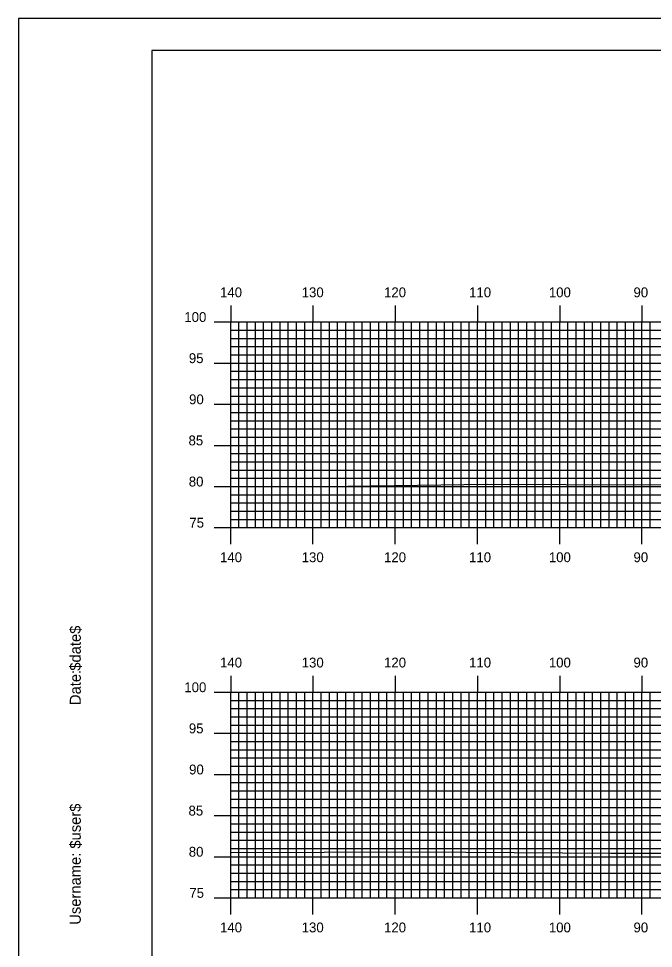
# Model space of a CAD drawing. Extents: x 1757069 to 1757412, y 442591 to 442811.
# Drawn here: x 1757068.8 to 1757146, y 442697.5 to 442810.5 of the extents above; entities that cross this region are included whole.
import ezdxf

# ---------------------------------------------------------------- set-up
doc = ezdxf.new("R2010")
doc.units = 0
for name, color, linetype in [('BORDER', 7, 'Continuous'), ('H_V ANNOTATION', 7, 'Continuous'), ('MAJOR', 7, 'Continuous'), ('MINOR', 7, 'Continuous'), ('PLOT BOUNDARY', 7, 'Continuous'), ('S_Roadway_Centerline', 7, 'Continuous')]:
    doc.layers.add(name, color=color, linetype=linetype)

msp = doc.modelspace()

# ---------------------------------------------------------------- linework, layer by layer
at = {"layer": 'BORDER'}
msp.add_lwpolyline([(1757085, 442596.67), (1757405, 442596.67), (1757405, 442806.67), (1757085, 442806.67)], close=True, dxfattribs=at)
at = {"layer": 'MAJOR'}
for p, q in [((1757094.6, 442775.67), (1757094.6, 442773.67)), ((1757104.6, 442775.67), (1757104.6, 442773.67)), ((1757114.6, 442775.67), (1757114.6, 442773.67)), ((1757124.6, 442775.67), (1757124.6, 442773.67)), ((1757134.6, 442775.67), (1757134.6, 442773.67)), ((1757144.6, 442775.67), (1757144.6, 442773.67)), ((1757092.59, 442773.67), (1757094.6, 442773.67)), ((1757094.6, 442773.67), (1757374.6, 442773.67)), ((1757094.6, 442748.67), (1757094.6, 442773.67)), ((1757094.6, 442748.67), (1757094.6, 442773.67)), ((1757094.6, 442773.67), (1757374.6, 442773.67)), ((1757104.6, 442748.67), (1757104.6, 442773.67)), ((1757114.6, 442748.67), (1757114.6, 442773.67)), ((1757124.6, 442748.67), (1757124.6, 442773.67)), ((1757134.6, 442748.67), (1757134.6, 442773.67)), ((1757144.6, 442748.67), (1757144.6, 442773.67)), ((1757092.59, 442768.67), (1757094.6, 442768.67)), ((1757094.6, 442768.67), (1757374.6, 442768.67)), ((1757092.59, 442763.67), (1757094.6, 442763.67)), ((1757094.6, 442763.67), (1757374.6, 442763.67)), ((1757092.59, 442758.67), (1757094.6, 442758.67)), ((1757094.6, 442758.67), (1757374.6, 442758.67)), ((1757092.59, 442753.67), (1757094.6, 442753.67)), ((1757094.6, 442753.67), (1757374.6, 442753.67)), ((1757092.59, 442748.67), (1757094.6, 442748.67)), ((1757094.6, 442748.67), (1757374.6, 442748.67)), ((1757094.6, 442748.67), (1757374.6, 442748.67)), ((1757094.6, 442746.66), (1757094.6, 442748.67)), ((1757104.6, 442746.66), (1757104.6, 442748.67)), ((1757114.6, 442746.66), (1757114.6, 442748.67)), ((1757124.6, 442746.66), (1757124.6, 442748.67)), ((1757134.6, 442746.66), (1757134.6, 442748.67)), ((1757144.6, 442746.66), (1757144.6, 442748.67)), ((1757094.6, 442730.67), (1757094.6, 442728.67)), ((1757104.6, 442730.67), (1757104.6, 442728.67)), ((1757114.6, 442730.67), (1757114.6, 442728.67)), ((1757124.6, 442730.67), (1757124.6, 442728.67)), ((1757134.6, 442730.67), (1757134.6, 442728.67)), ((1757144.6, 442730.67), (1757144.6, 442728.67)), ((1757092.59, 442728.67), (1757094.6, 442728.67)), ((1757094.6, 442728.67), (1757374.6, 442728.67)), ((1757094.6, 442703.67), (1757094.6, 442728.67)), ((1757094.6, 442703.67), (1757094.6, 442728.67)), ((1757094.6, 442728.67), (1757374.6, 442728.67)), ((1757104.6, 442703.67), (1757104.6, 442728.67)), ((1757114.6, 442703.67), (1757114.6, 442728.67)), ((1757124.6, 442703.67), (1757124.6, 442728.67)), ((1757134.6, 442703.67), (1757134.6, 442728.67)), ((1757144.6, 442703.67), (1757144.6, 442728.67)), ((1757092.59, 442723.67), (1757094.6, 442723.67)), ((1757094.6, 442723.67), (1757374.6, 442723.67)), ((1757092.59, 442718.67), (1757094.6, 442718.67)), ((1757094.6, 442718.67), (1757374.6, 442718.67)), ((1757092.59, 442713.67), (1757094.6, 442713.67)), ((1757094.6, 442713.67), (1757374.6, 442713.67)), ((1757092.59, 442708.67), (1757094.6, 442708.67)), ((1757094.6, 442708.67), (1757374.6, 442708.67)), ((1757092.59, 442703.67), (1757094.6, 442703.67)), ((1757094.6, 442703.67), (1757374.6, 442703.67)), ((1757094.6, 442703.67), (1757374.6, 442703.67)), ((1757094.6, 442701.66), (1757094.6, 442703.67)), ((1757104.6, 442701.66), (1757104.6, 442703.67)), ((1757114.6, 442701.66), (1757114.6, 442703.67)), ((1757124.6, 442701.66), (1757124.6, 442703.67)), ((1757134.6, 442701.66), (1757134.6, 442703.67)), ((1757144.6, 442701.66), (1757144.6, 442703.67))]:
    msp.add_line(p, q, dxfattribs=at)
at = {"layer": 'MINOR'}
for p, q in [((1757095.6, 442748.67), (1757095.6, 442773.67)), ((1757096.6, 442748.67), (1757096.6, 442773.67)), ((1757097.6, 442748.67), (1757097.6, 442773.67)), ((1757098.6, 442748.67), (1757098.6, 442773.67)), ((1757099.6, 442748.67), (1757099.6, 442773.67)), ((1757100.6, 442748.67), (1757100.6, 442773.67)), ((1757101.6, 442748.67), (1757101.6, 442773.67)), ((1757102.6, 442748.67), (1757102.6, 442773.67)), ((1757103.6, 442748.67), (1757103.6, 442773.67)), ((1757105.6, 442748.67), (1757105.6, 442773.67)), ((1757106.6, 442748.67), (1757106.6, 442773.67)), ((1757107.6, 442748.67), (1757107.6, 442773.67)), ((1757108.6, 442748.67), (1757108.6, 442773.67)), ((1757109.6, 442748.67), (1757109.6, 442773.67)), ((1757110.6, 442748.67), (1757110.6, 442773.67)), ((1757111.6, 442748.67), (1757111.6, 442773.67)), ((1757112.6, 442748.67), (1757112.6, 442773.67)), ((1757113.6, 442748.67), (1757113.6, 442773.67)), ((1757115.6, 442748.67), (1757115.6, 442773.67)), ((1757116.6, 442748.67), (1757116.6, 442773.67)), ((1757117.6, 442748.67), (1757117.6, 442773.67)), ((1757118.6, 442748.67), (1757118.6, 442773.67)), ((1757119.6, 442748.67), (1757119.6, 442773.67)), ((1757120.6, 442748.67), (1757120.6, 442773.67)), ((1757121.6, 442748.67), (1757121.6, 442773.67)), ((1757122.6, 442748.67), (1757122.6, 442773.67)), ((1757123.6, 442748.67), (1757123.6, 442773.67)), ((1757125.6, 442748.67), (1757125.6, 442773.67)), ((1757126.6, 442748.67), (1757126.6, 442773.67)), ((1757127.6, 442748.67), (1757127.6, 442773.67)), ((1757128.6, 442748.67), (1757128.6, 442773.67)), ((1757129.6, 442748.67), (1757129.6, 442773.67)), ((1757130.6, 442748.67), (1757130.6, 442773.67)), ((1757131.6, 442748.67), (1757131.6, 442773.67)), ((1757132.6, 442748.67), (1757132.6, 442773.67)), ((1757133.6, 442748.67), (1757133.6, 442773.67)), ((1757135.6, 442748.67), (1757135.6, 442773.67)), ((1757136.6, 442748.67), (1757136.6, 442773.67)), ((1757137.6, 442748.67), (1757137.6, 442773.67)), ((1757138.6, 442748.67), (1757138.6, 442773.67)), ((1757139.6, 442748.67), (1757139.6, 442773.67)), ((1757140.6, 442748.67), (1757140.6, 442773.67)), ((1757141.6, 442748.67), (1757141.6, 442773.67)), ((1757142.6, 442748.67), (1757142.6, 442773.67)), ((1757143.6, 442748.67), (1757143.6, 442773.67)), ((1757145.6, 442748.67), (1757145.6, 442773.67)), ((1757094.6, 442772.67), (1757374.6, 442772.67)), ((1757094.6, 442772.67), (1757096.6, 442772.67)), ((1757094.6, 442771.67), (1757374.6, 442771.67)), ((1757094.6, 442771.67), (1757096.6, 442771.67)), ((1757094.6, 442770.67), (1757374.6, 442770.67)), ((1757094.6, 442770.67), (1757096.6, 442770.67)), ((1757094.6, 442769.67), (1757374.6, 442769.67)), ((1757094.6, 442769.67), (1757096.6, 442769.67)), ((1757094.6, 442767.67), (1757374.6, 442767.67)), ((1757094.6, 442767.67), (1757096.6, 442767.67)), ((1757094.6, 442766.67), (1757374.6, 442766.67)), ((1757094.6, 442766.67), (1757096.6, 442766.67)), ((1757094.6, 442765.67), (1757374.6, 442765.67)), ((1757094.6, 442765.67), (1757096.6, 442765.67)), ((1757094.6, 442764.67), (1757374.6, 442764.67)), ((1757094.6, 442764.67), (1757096.6, 442764.67)), ((1757094.6, 442762.67), (1757374.6, 442762.67)), ((1757094.6, 442762.67), (1757096.6, 442762.67)), ((1757094.6, 442761.67), (1757374.6, 442761.67)), ((1757094.6, 442761.67), (1757096.6, 442761.67)), ((1757094.6, 442760.67), (1757374.6, 442760.67)), ((1757094.6, 442760.67), (1757096.6, 442760.67)), ((1757094.6, 442759.67), (1757374.6, 442759.67)), ((1757094.6, 442759.67), (1757096.6, 442759.67)), ((1757094.6, 442757.67), (1757374.6, 442757.67)), ((1757094.6, 442757.67), (1757096.6, 442757.67)), ((1757094.6, 442756.67), (1757374.6, 442756.67)), ((1757094.6, 442756.67), (1757096.6, 442756.67)), ((1757094.6, 442755.67), (1757374.6, 442755.67)), ((1757094.6, 442755.67), (1757096.6, 442755.67)), ((1757094.6, 442754.67), (1757374.6, 442754.67)), ((1757094.6, 442754.67), (1757096.6, 442754.67)), ((1757094.6, 442752.67), (1757374.6, 442752.67)), ((1757094.6, 442752.67), (1757096.6, 442752.67)), ((1757094.6, 442751.67), (1757374.6, 442751.67)), ((1757094.6, 442751.67), (1757096.6, 442751.67)), ((1757094.6, 442750.67), (1757374.6, 442750.67)), ((1757094.6, 442750.67), (1757096.6, 442750.67)), ((1757094.6, 442749.67), (1757374.6, 442749.67)), ((1757094.6, 442749.67), (1757096.6, 442749.67)), ((1757095.6, 442703.67), (1757095.6, 442728.67)), ((1757096.6, 442703.67), (1757096.6, 442728.67)), ((1757097.6, 442703.67), (1757097.6, 442728.67)), ((1757098.6, 442703.67), (1757098.6, 442728.67)), ((1757099.6, 442703.67), (1757099.6, 442728.67)), ((1757100.6, 442703.67), (1757100.6, 442728.67)), ((1757101.6, 442703.67), (1757101.6, 442728.67)), ((1757102.6, 442703.67), (1757102.6, 442728.67)), ((1757103.6, 442703.67), (1757103.6, 442728.67)), ((1757105.6, 442703.67), (1757105.6, 442728.67)), ((1757106.6, 442703.67), (1757106.6, 442728.67)), ((1757107.6, 442703.67), (1757107.6, 442728.67)), ((1757108.6, 442703.67), (1757108.6, 442728.67)), ((1757109.6, 442703.67), (1757109.6, 442728.67)), ((1757110.6, 442703.67), (1757110.6, 442728.67)), ((1757111.6, 442703.67), (1757111.6, 442728.67)), ((1757112.6, 442703.67), (1757112.6, 442728.67)), ((1757113.6, 442703.67), (1757113.6, 442728.67)), ((1757115.6, 442703.67), (1757115.6, 442728.67)), ((1757116.6, 442703.67), (1757116.6, 442728.67)), ((1757117.6, 442703.67), (1757117.6, 442728.67)), ((1757118.6, 442703.67), (1757118.6, 442728.67)), ((1757119.6, 442703.67), (1757119.6, 442728.67)), ((1757120.6, 442703.67), (1757120.6, 442728.67)), ((1757121.6, 442703.67), (1757121.6, 442728.67)), ((1757122.6, 442703.67), (1757122.6, 442728.67)), ((1757123.6, 442703.67), (1757123.6, 442728.67)), ((1757125.6, 442703.67), (1757125.6, 442728.67)), ((1757126.6, 442703.67), (1757126.6, 442728.67)), ((1757127.6, 442703.67), (1757127.6, 442728.67)), ((1757128.6, 442703.67), (1757128.6, 442728.67)), ((1757129.6, 442703.67), (1757129.6, 442728.67)), ((1757130.6, 442703.67), (1757130.6, 442728.67)), ((1757131.6, 442703.67), (1757131.6, 442728.67)), ((1757132.6, 442703.67), (1757132.6, 442728.67)), ((1757133.6, 442703.67), (1757133.6, 442728.67)), ((1757135.6, 442703.67), (1757135.6, 442728.67)), ((1757136.6, 442703.67), (1757136.6, 442728.67)), ((1757137.6, 442703.67), (1757137.6, 442728.67)), ((1757138.6, 442703.67), (1757138.6, 442728.67)), ((1757139.6, 442703.67), (1757139.6, 442728.67)), ((1757140.6, 442703.67), (1757140.6, 442728.67)), ((1757141.6, 442703.67), (1757141.6, 442728.67)), ((1757142.6, 442703.67), (1757142.6, 442728.67)), ((1757143.6, 442703.67), (1757143.6, 442728.67)), ((1757145.6, 442703.67), (1757145.6, 442728.67)), ((1757094.6, 442727.67), (1757374.6, 442727.67)), ((1757094.6, 442727.67), (1757096.6, 442727.67)), ((1757094.6, 442726.67), (1757374.6, 442726.67)), ((1757094.6, 442726.67), (1757096.6, 442726.67)), ((1757094.6, 442725.67), (1757374.6, 442725.67)), ((1757094.6, 442725.67), (1757096.6, 442725.67)), ((1757094.6, 442724.67), (1757374.6, 442724.67)), ((1757094.6, 442724.67), (1757096.6, 442724.67)), ((1757094.6, 442722.67), (1757374.6, 442722.67)), ((1757094.6, 442722.67), (1757096.6, 442722.67)), ((1757094.6, 442721.67), (1757374.6, 442721.67)), ((1757094.6, 442721.67), (1757096.6, 442721.67)), ((1757094.6, 442720.67), (1757374.6, 442720.67)), ((1757094.6, 442720.67), (1757096.6, 442720.67)), ((1757094.6, 442719.67), (1757374.6, 442719.67)), ((1757094.6, 442719.67), (1757096.6, 442719.67)), ((1757094.6, 442717.67), (1757374.6, 442717.67)), ((1757094.6, 442717.67), (1757096.6, 442717.67)), ((1757094.6, 442716.67), (1757374.6, 442716.67)), ((1757094.6, 442716.67), (1757096.6, 442716.67)), ((1757094.6, 442715.67), (1757374.6, 442715.67)), ((1757094.6, 442715.67), (1757096.6, 442715.67)), ((1757094.6, 442714.67), (1757374.6, 442714.67)), ((1757094.6, 442714.67), (1757096.6, 442714.67)), ((1757094.6, 442712.67), (1757374.6, 442712.67)), ((1757094.6, 442712.67), (1757096.6, 442712.67)), ((1757094.6, 442711.67), (1757374.6, 442711.67)), ((1757094.6, 442711.67), (1757096.6, 442711.67)), ((1757094.6, 442710.67), (1757374.6, 442710.67)), ((1757094.6, 442710.67), (1757096.6, 442710.67)), ((1757094.6, 442709.67), (1757374.6, 442709.67)), ((1757094.6, 442709.67), (1757096.6, 442709.67)), ((1757094.6, 442707.67), (1757374.6, 442707.67)), ((1757094.6, 442707.67), (1757096.6, 442707.67)), ((1757094.6, 442706.67), (1757374.6, 442706.67)), ((1757094.6, 442706.67), (1757096.6, 442706.67)), ((1757094.6, 442705.67), (1757374.6, 442705.67)), ((1757094.6, 442705.67), (1757096.6, 442705.67)), ((1757094.6, 442704.67), (1757374.6, 442704.67)), ((1757094.6, 442704.67), (1757096.6, 442704.67))]:
    msp.add_line(p, q, dxfattribs=at)
at = {"layer": 'PLOT BOUNDARY'}
msp.add_lwpolyline([(1757068.81, 442590.55), (1757408.81, 442590.55), (1757408.81, 442810.55), (1757068.81, 442810.55)], close=True, dxfattribs=at)
at = {"layer": 'S_Roadway_Centerline'}
for points in [[(1757094.6, 442753.7), (1757106.02, 442753.69), (1757125.8, 442753.96), (1757135.34, 442753.91), (1757159.12, 442753.84), (1757182.03, 442754.12), (1757202.03, 442754.31), (1757204.09, 442754.32), (1757230.57, 442754.75), (1757249.03, 442754.84), (1757258.63, 442754.86), (1757284.4, 442755.15), (1757295.54, 442755.17), (1757319.95, 442754.95), (1757333.06, 442754.89), (1757374.6, 442754.64)], [(1757094.6, 442709.18), (1757117.33, 442709.26), (1757140.81, 442709.08), (1757149.64, 442709.11), (1757165.92, 442709.27), (1757181.5, 442709.37), (1757191.75, 442709.55), (1757206.83, 442709.71), (1757242.69, 442709.94), (1757244.49, 442709.95), (1757245.67, 442709.95), (1757285.02, 442710.21), (1757285.15, 442710.21), (1757316.08, 442710.1), (1757319.99, 442710.08), (1757358.79, 442710.05), (1757374.6, 442710.01)]]:
    msp.add_lwpolyline(points, dxfattribs=at)

# ---------------------------------------------------------------- texts
at = {"layer": 'BORDER'}
for s, p in [('$date$', (1757076.37, 442731.28)), ('$date$', (1757076.37, 442731.28)), ('Date:', (1757076.37, 442727.1)), ('Date:', (1757076.37, 442727.1)), ('$user$', (1757076.37, 442709.65)), ('$user$', (1757076.37, 442709.65)), ('Username:', (1757076.37, 442700.4)), ('Username:', (1757076.37, 442700.4))]:
    msp.add_text(s, height=1.339, rotation=90, dxfattribs=at).set_placement(p)
at = {"layer": 'H_V ANNOTATION'}
for s, p in [('140', (1757093.3, 442776.67)), ('130', (1757103.23, 442776.67)), ('120', (1757113.24, 442776.67)), ('110', (1757123.58, 442776.67)), ('100', (1757133.28, 442776.67)), ('90', (1757143.57, 442776.67)), ('100', (1757088.96, 442773.67)), ('95', (1757089.51, 442768.67)), ('90', (1757089.54, 442763.67)), ('85', (1757089.47, 442758.67)), ('80', (1757089.5, 442753.67)), ('75', (1757089.57, 442748.67)), ('140', (1757093.3, 442744.47)), ('130', (1757103.23, 442744.47)), ('120', (1757113.24, 442744.47)), ('110', (1757123.58, 442744.47)), ('100', (1757133.28, 442744.47)), ('90', (1757143.57, 442744.47)), ('140', (1757093.3, 442731.67)), ('130', (1757103.23, 442731.67)), ('120', (1757113.24, 442731.67)), ('110', (1757123.58, 442731.67)), ('100', (1757133.28, 442731.67)), ('90', (1757143.57, 442731.67)), ('100', (1757088.96, 442728.67)), ('95', (1757089.51, 442723.67)), ('90', (1757089.54, 442718.67)), ('85', (1757089.47, 442713.67)), ('80', (1757089.5, 442708.67)), ('75', (1757089.57, 442703.67)), ('140', (1757093.3, 442699.47)), ('130', (1757103.23, 442699.47)), ('120', (1757113.24, 442699.47)), ('110', (1757123.58, 442699.47)), ('100', (1757133.28, 442699.47)), ('90', (1757143.57, 442699.47))]:
    msp.add_text(s, height=1.2, dxfattribs=at).set_placement(p)
at = {"layer": 'MAJOR'}
for p in [(1757094.59, 442748.67), (1757094.59, 442703.67)]:
    msp.add_text('-', height=0.012, dxfattribs=at).set_placement(p)

doc.saveas('drawing.dxf')
